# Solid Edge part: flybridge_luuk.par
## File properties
Author: Mac
Template: Normal.par
Last saved by: Mac
Revision: 6
Application: Solid Edge
Material: Aluminum, 1060
Face Style: Aluminum
Fill Style: ANSI38(Aluminum)
Virtual Style: Polished aluminum
Coef. of Thermal Exp: 2.3e-05
Thermal Conductivity: 221.0
Specific Heat: 920.0
Modulus of Elasticity: 68947570000.0
Poission's Ratio: 0.33
Yield Stress: 27579028.0
Ultimate Stress: 68947570.0
Elongation: 0.0
Density: 2712,000 kg/m^3
Accuracy: 0,990
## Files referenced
..\Asm17.asm
5C:\Documents and Settings\Mac\Desktop\paat6\Asm17.asm
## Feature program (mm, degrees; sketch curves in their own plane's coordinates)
sketch for "unnamed Protrusion 1" plane through (0, 0, 0) normal (0, 0, 1) x-axis (1, 0, 0)
  line (-4.427, 4.2739) -> (-4.427, -4.3261)
  arc centre (-4.227, -4.3261) radius 0.2 from (-4.227, -4.5261) to (-4.427, -4.3261) cw
  line (4.4988, -4.5261) -> (-4.227, -4.5261)
  arc centre (4.4988, -4.3261) radius 0.2 from (4.6988, -4.3261) to (4.4988, -4.5261) cw
  line (4.6988, -4.3261) -> (4.6988, 4.2739)
  arc centre (4.4988, 4.2739) radius 0.2 from (4.6988, 4.2739) to (4.4988, 4.4739) ccw
  line (4.4988, 4.4739) -> (-4.227, 4.4739)
  arc centre (-4.227, 4.2739) radius 0.2 from (-4.227, 4.4739) to (-4.427, 4.2739) ccw
extrude "unnamed Protrusion 1" add finite 0.4 along +normal
swept protrusion "SweptProtrusion_1"  CrossSections_Plane1_FractionOfCurve = 1
swept protrusion "SweptProtrusion_2"  CrossSections_Plane1_FractionOfCurve = 1
sketch for "ExtrudedProtrusion_2" plane through (0.1359, -0.0261, 0) normal (0, 0, -1) x-axis (1, 0, 0)
  line (-4.5629, -4.3) -> (-4.5629, 4.3)
  arc centre (-4.3629, 4.3) radius 0.2 from (-4.5629, 4.3) to (-4.3629, 4.5) cw
  line (-4.3629, 4.5) -> (4.3629, 4.5)
  arc centre (4.3629, 4.3) radius 0.2 from (4.3629, 4.5) to (4.5629, 4.3) cw
  line (4.5629, 4.3) -> (4.5629, -4.3)
  arc centre (4.3629, -4.3) radius 0.2 from (4.5629, -4.3) to (4.3629, -4.5) cw
  line (4.3629, -4.5) -> (-4.3629, -4.5)
  arc centre (-4.3629, -4.3) radius 0.2 from (-4.3629, -4.5) to (-4.5629, -4.3) cw
extrude "ExtrudedProtrusion_2" add finite 0.1 along +normal
sketch for "ExtrudedCutout_1" plane through (0.1359, -0.0261, -0.1) normal (0, 0, -1) x-axis (1, 0, 0)
  line (-4.5229, -4.3) -> (-4.5229, 4.3)
  arc centre (-4.3629, 4.3) radius 0.16 from (-4.5229, 4.3) to (-4.3629, 4.46) cw
  line (-4.3629, 4.46) -> (4.3629, 4.46)
  arc centre (4.3629, 4.3) radius 0.16 from (4.3629, 4.46) to (4.5229, 4.3) cw
  line (4.5229, 4.3) -> (4.5229, -4.3)
  arc centre (4.3629, -4.3) radius 0.16 from (4.5229, -4.3) to (4.3629, -4.46) cw
  line (4.3629, -4.46) -> (-4.3629, -4.46)
  arc centre (-4.3629, -4.3) radius 0.16 from (-4.3629, -4.46) to (-4.5229, -4.3) cw
extrude "ExtrudedCutout_1" cut finite 0.44 along -normal
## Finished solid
Body 1: solid body, 36 faces, 88 edges, 56 vertices.
  Faces by surface: plane 16, cylinder 12, cone 4, torus 4
  Edges by curve: line 52, circle 36
Bounding box of the edges (mm; curved faces can reach further): 10.017 x 9.891 x 0.500, from (-4.8727, -4.9718, -0.1) to (5.1444, 4.9196, 0.4).
Cylindrical faces by radius (mm): R0.0177 x4, R0.16 x4, R0.2 x4
Conical faces (half-angle, radius in mm at the cone's reference point): 50 deg R0.2 x2, 50 deg R0.6394 x2
Toroidal faces (ring radius, tube radius in mm): R0.628 r0.0177 x4
Planar faces by outward normal: +x 2, +y 2, +z 1, -x 2, -y 2, -z 3, oblique 4
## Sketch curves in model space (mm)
arc centre (-4.227, 4.2739, 0.34) radius 0.2 from (-4.227, 4.4739, 0.34) through (-4.3725, 4.4112, 0.34) to (-4.427, 4.2739, 0.34)
line (-4.427, 4.2739, 0.34) -> (-4.427, -4.3261, 0.34)
arc centre (-4.227, -4.3261, 0.34) radius 0.2 from (-4.427, -4.3261, 0.34) through (-4.3643, -4.4715, 0.34) to (-4.227, -4.5261, 0.34)
line (-4.227, -4.5261, 0.34) -> (4.4988, -4.5261, 0.34)
arc centre (4.4988, -4.3261, 0.34) radius 0.2 from (4.4988, -4.5261, 0.34) through (4.6442, -4.4633, 0.34) to (4.6988, -4.3261, 0.34)
line (4.6988, -4.3261, 0.34) -> (4.6988, 4.2739, 0.34)
arc centre (4.4988, 4.2739, 0.34) radius 0.2 from (4.6988, 4.2739, 0.34) through (4.636, 4.4194, 0.34) to (4.4988, 4.4739, 0.34)
line (4.4988, 4.4739, 0.34) -> (-4.227, 4.4739, 0.34)
arc centre (-4.227, -4.3261, 0) radius 0.2 from (-4.227, -4.5261, 0) through (-4.3725, -4.4633, 0) to (-4.427, -4.3261, 0)
line (4.4988, -4.5261, 0) -> (-4.227, -4.5261, 0)
arc centre (4.4988, -4.3261, 0) radius 0.2 from (4.6988, -4.3261, 0) through (4.636, -4.4715, 0) to (4.4988, -4.5261, 0)
line (4.6988, -4.3261, 0) -> (4.6988, 4.2739, 0)
arc centre (4.4988, 4.2739, 0) radius 0.2 from (4.6988, 4.2739, 0) through (4.636, 4.4194, 0) to (4.4988, 4.4739, 0)
line (4.4988, 4.4739, 0) -> (-4.227, 4.4739, 0)
arc centre (-4.227, 4.2739, 0) radius 0.2 from (-4.227, 4.4739, 0) through (-4.3725, 4.4112, 0) to (-4.427, 4.2739, 0)
line (-4.427, 4.2739, 0) -> (-4.427, -4.3261, 0)
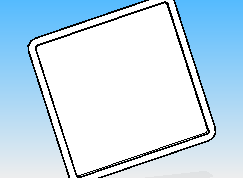
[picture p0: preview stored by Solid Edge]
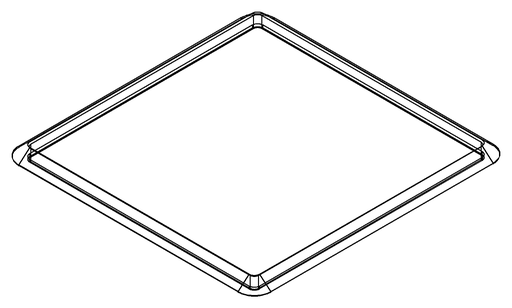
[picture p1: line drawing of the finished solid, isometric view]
